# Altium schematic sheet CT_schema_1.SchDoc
size 459 x 258 mm
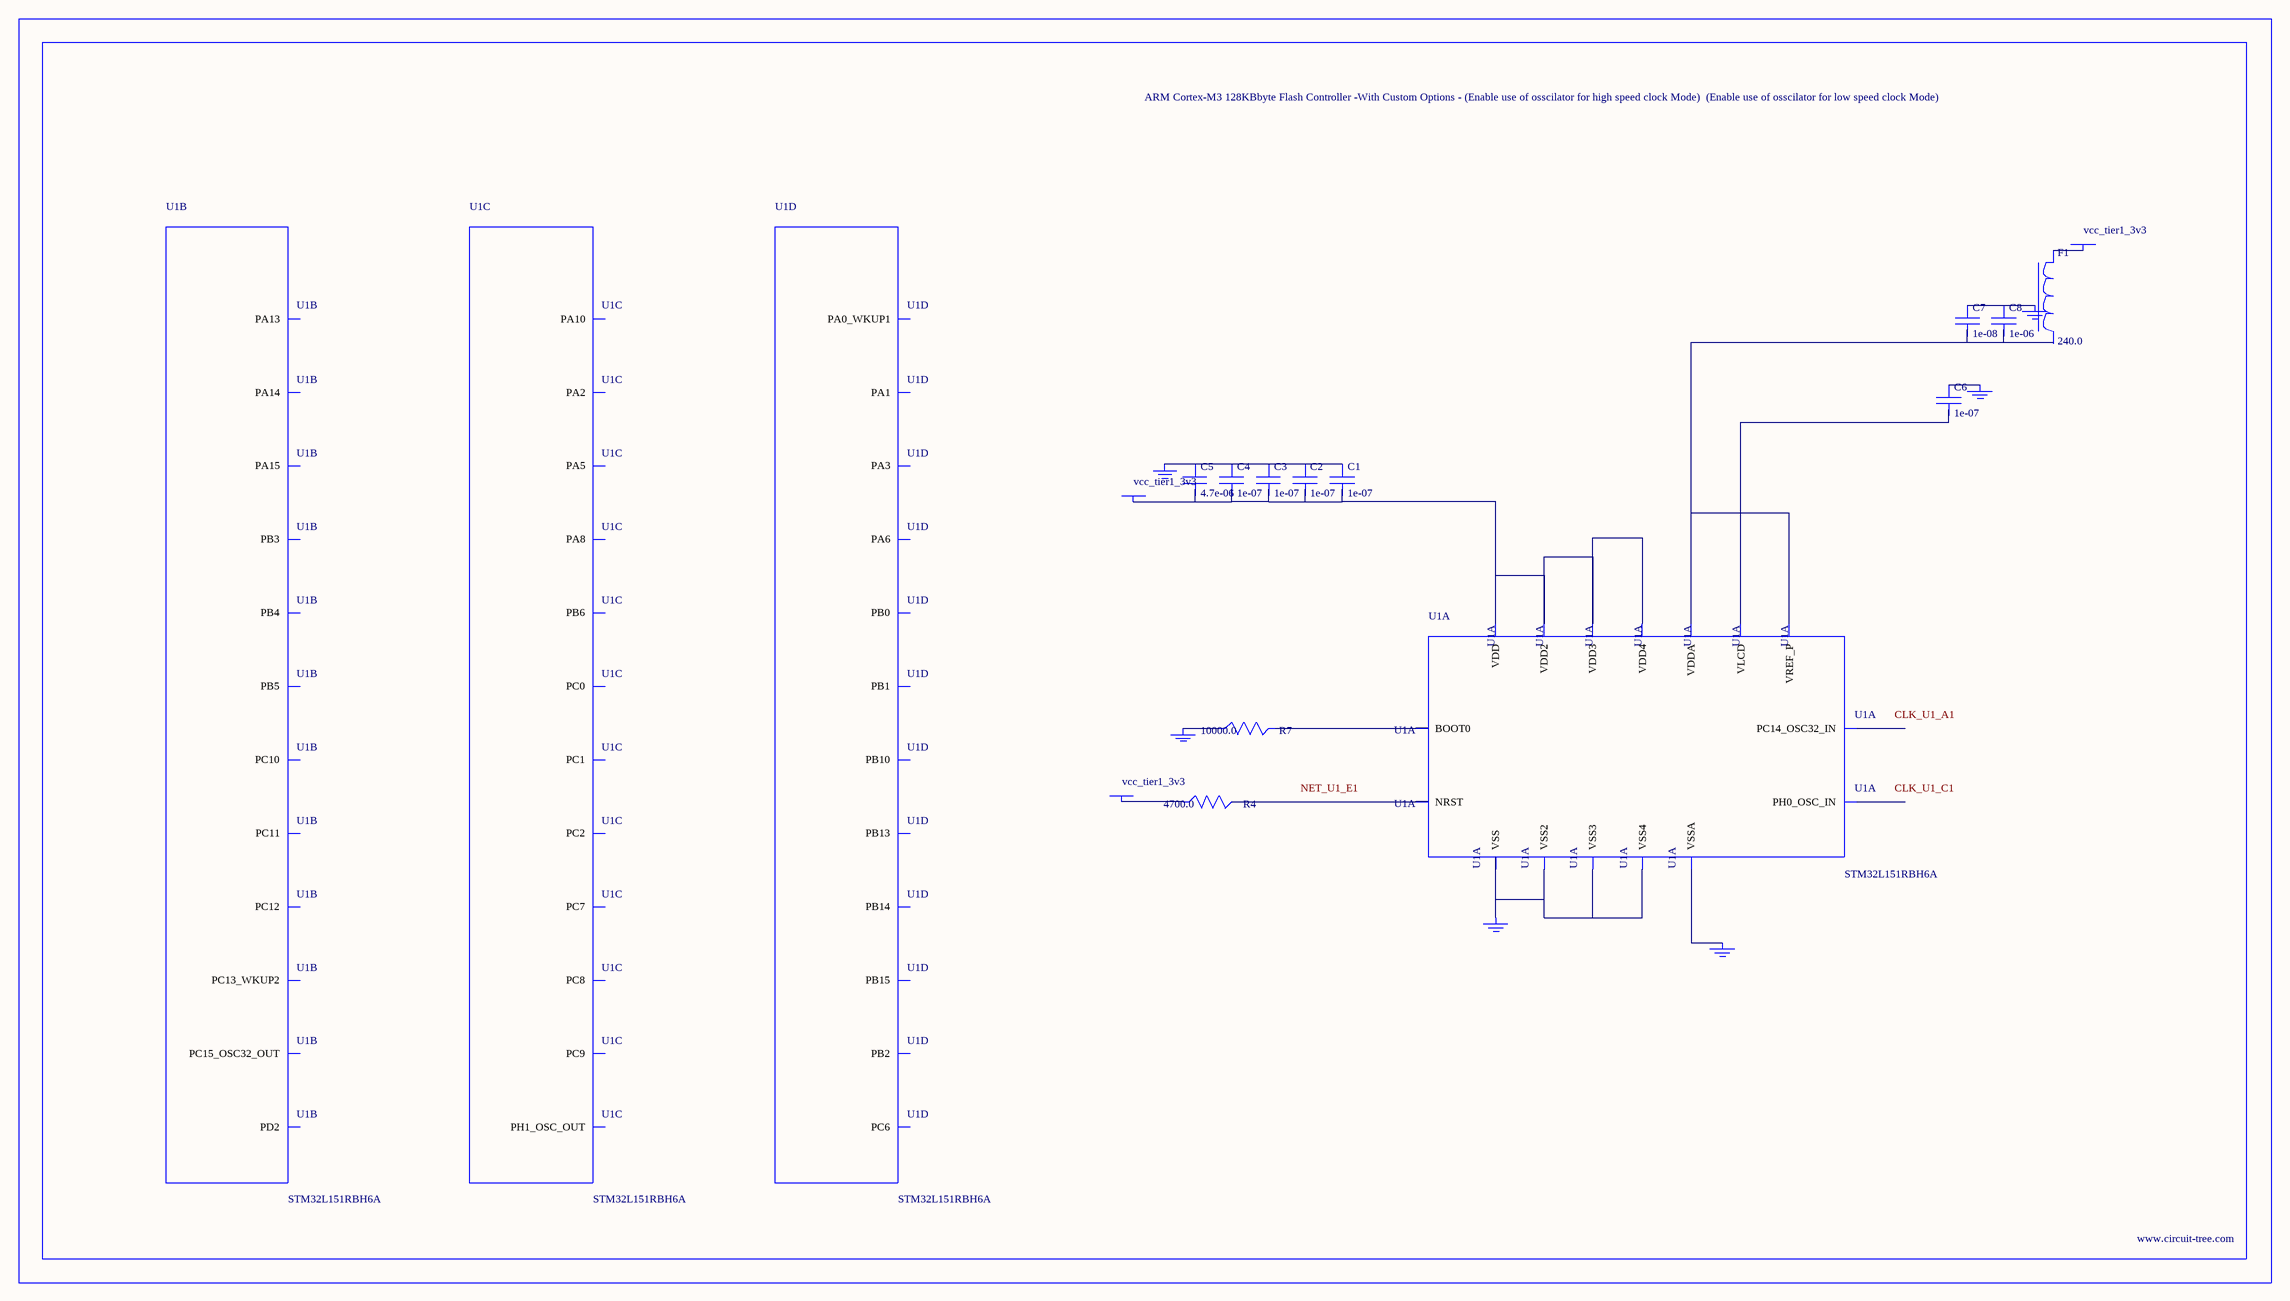
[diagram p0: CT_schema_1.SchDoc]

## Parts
BORDER0  (no value)
C1  1e-07  [C0603]
C2  1e-07  [C0603]
C3  1e-07  [C0603]
C4  1e-07  [C0603]
C5  4.7e-06  [C0603]
C6  1e-07  [C0603]
C7  1e-08  [C0603]
C8  1e-06  [C0603]
F1  240.0  [L0603]
GND_INSTANCE_0_0  (no value)
GND_INSTANCE_0_1  (no value)
GND_INSTANCE_0_2  (no value)
GND_INSTANCE_0_3  (no value)
GND_INSTANCE_0_4  (no value)
GND_INSTANCE_0_5  (no value)
POWER_INSTANCE_0_0  vcc_tier1_3v3
POWER_INSTANCE_0_1  vcc_tier1_3v3
POWER_INSTANCE_0_2  vcc_tier1_3v3
R4  4700.0  [R0603]
R7  10000.0  [R0603]
U1  STM32L151RBH6A  [TFBGA64]  (parts A,B,C,D of 6)

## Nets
NetC1_1: C1.1 C2.1 C3.1 C4.1 C5.1 GND_INSTANCE_0_1.0(GND)
NetC1_2: C1.2 C2.2 C3.2 C4.2 C5.2 POWER_INSTANCE_0_1.0(PWR) U1.D2(VDD) U1.E4(VDD2) U1.E5(VDD3) U1.E6(VDD4)
NetC6_1: C6.1 GND_INSTANCE_0_2.0(GND)
NetC6_2: C6.2 U1.B2(VLCD)
NetC7_1: C7.1 C8.1 GND_INSTANCE_0_0.0(GND)
NetC7_2: C7.2 C8.2 U1.G1(VREF_P) U1.H1(VDDA)
NetF1_1: F1.1 POWER_INSTANCE_0_0.0(PWR)
NetGND_INSTANCE_0_3_0: GND_INSTANCE_0_3.0(GND) R7.1
NetGND_INSTANCE_0_4_0: GND_INSTANCE_0_4.0(GND) U1.F1(VSSA)
NetGND_INSTANCE_0_5_0: GND_INSTANCE_0_5.0(GND) U1.C2(VSS) U1.D4(VSS2) U1.D5(VSS3) U1.D6(VSS4)
NetPOWER_INSTANCE_0_2_0: POWER_INSTANCE_0_2.0(PWR) R4.1
NetR4_2: R4.2 U1.E1(NRST)
NetR7_2: R7.2 U1.B4(BOOT0)

Not connected (* = marked no-connect by the designer): F1 2; U1 A1(PC14_OSC32_IN) A2(PC13_WKUP2) A4(PB4) A5(PB3) A6(PA15) A7(PA14) A8(PA13) B1(PC15_OSC32_OUT) B5(PD2) B6(PC11) B7(PC10) C1(PH0_OSC_IN) C4(PB5) C5(PC12) C6(PA10) D1(PH1_OSC_OUT) D3(PB6) D7(PA8) D8(PC9) E2(PC1) E3(PC0) E7(PC7) E8(PC8) F2(PC2) F3(PA2) F4(PA5) F5(PB0) F6(PC6) F7(PB15) F8(PB14) G2(PA0_WKUP1) G3(PA3) G4(PA6) G5(PB1) G6(PB2) G7(PB10) G8(PB13) H2(PA1)

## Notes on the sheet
- Labels drawn without touching a wire or pin: CLK_U1_A1, CLK_U1_C1, NET_U1_E1

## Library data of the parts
BORDER0 = BORDER_PAGE0
C1-C4 C6 = 06035C104K4Z2A
C5 = GRM188R6YA475KE15D
C7 = 06035C103K4Z2A
C8 = C0603C105K3RACTU
F1 = Z0603C241ASMST
GND_INSTANCE_0_0-GND_INSTANCE_0_5 = GND
POWER_INSTANCE_0_0-POWER_INSTANCE_0_2 = PWR
R4 = RC0603JR-074K7L
R7 = RC0603JR-0710KL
